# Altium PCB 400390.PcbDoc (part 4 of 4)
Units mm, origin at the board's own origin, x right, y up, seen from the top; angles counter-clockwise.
Board outline 50.8 x 50.4 mm, 4 copper layers (Top Layer, Mid Layer 1, Mid Layer 2, Bottom Layer), stack 1.507 mm thick; 236 components, 197 nets, 1131 pads, 994 vias.
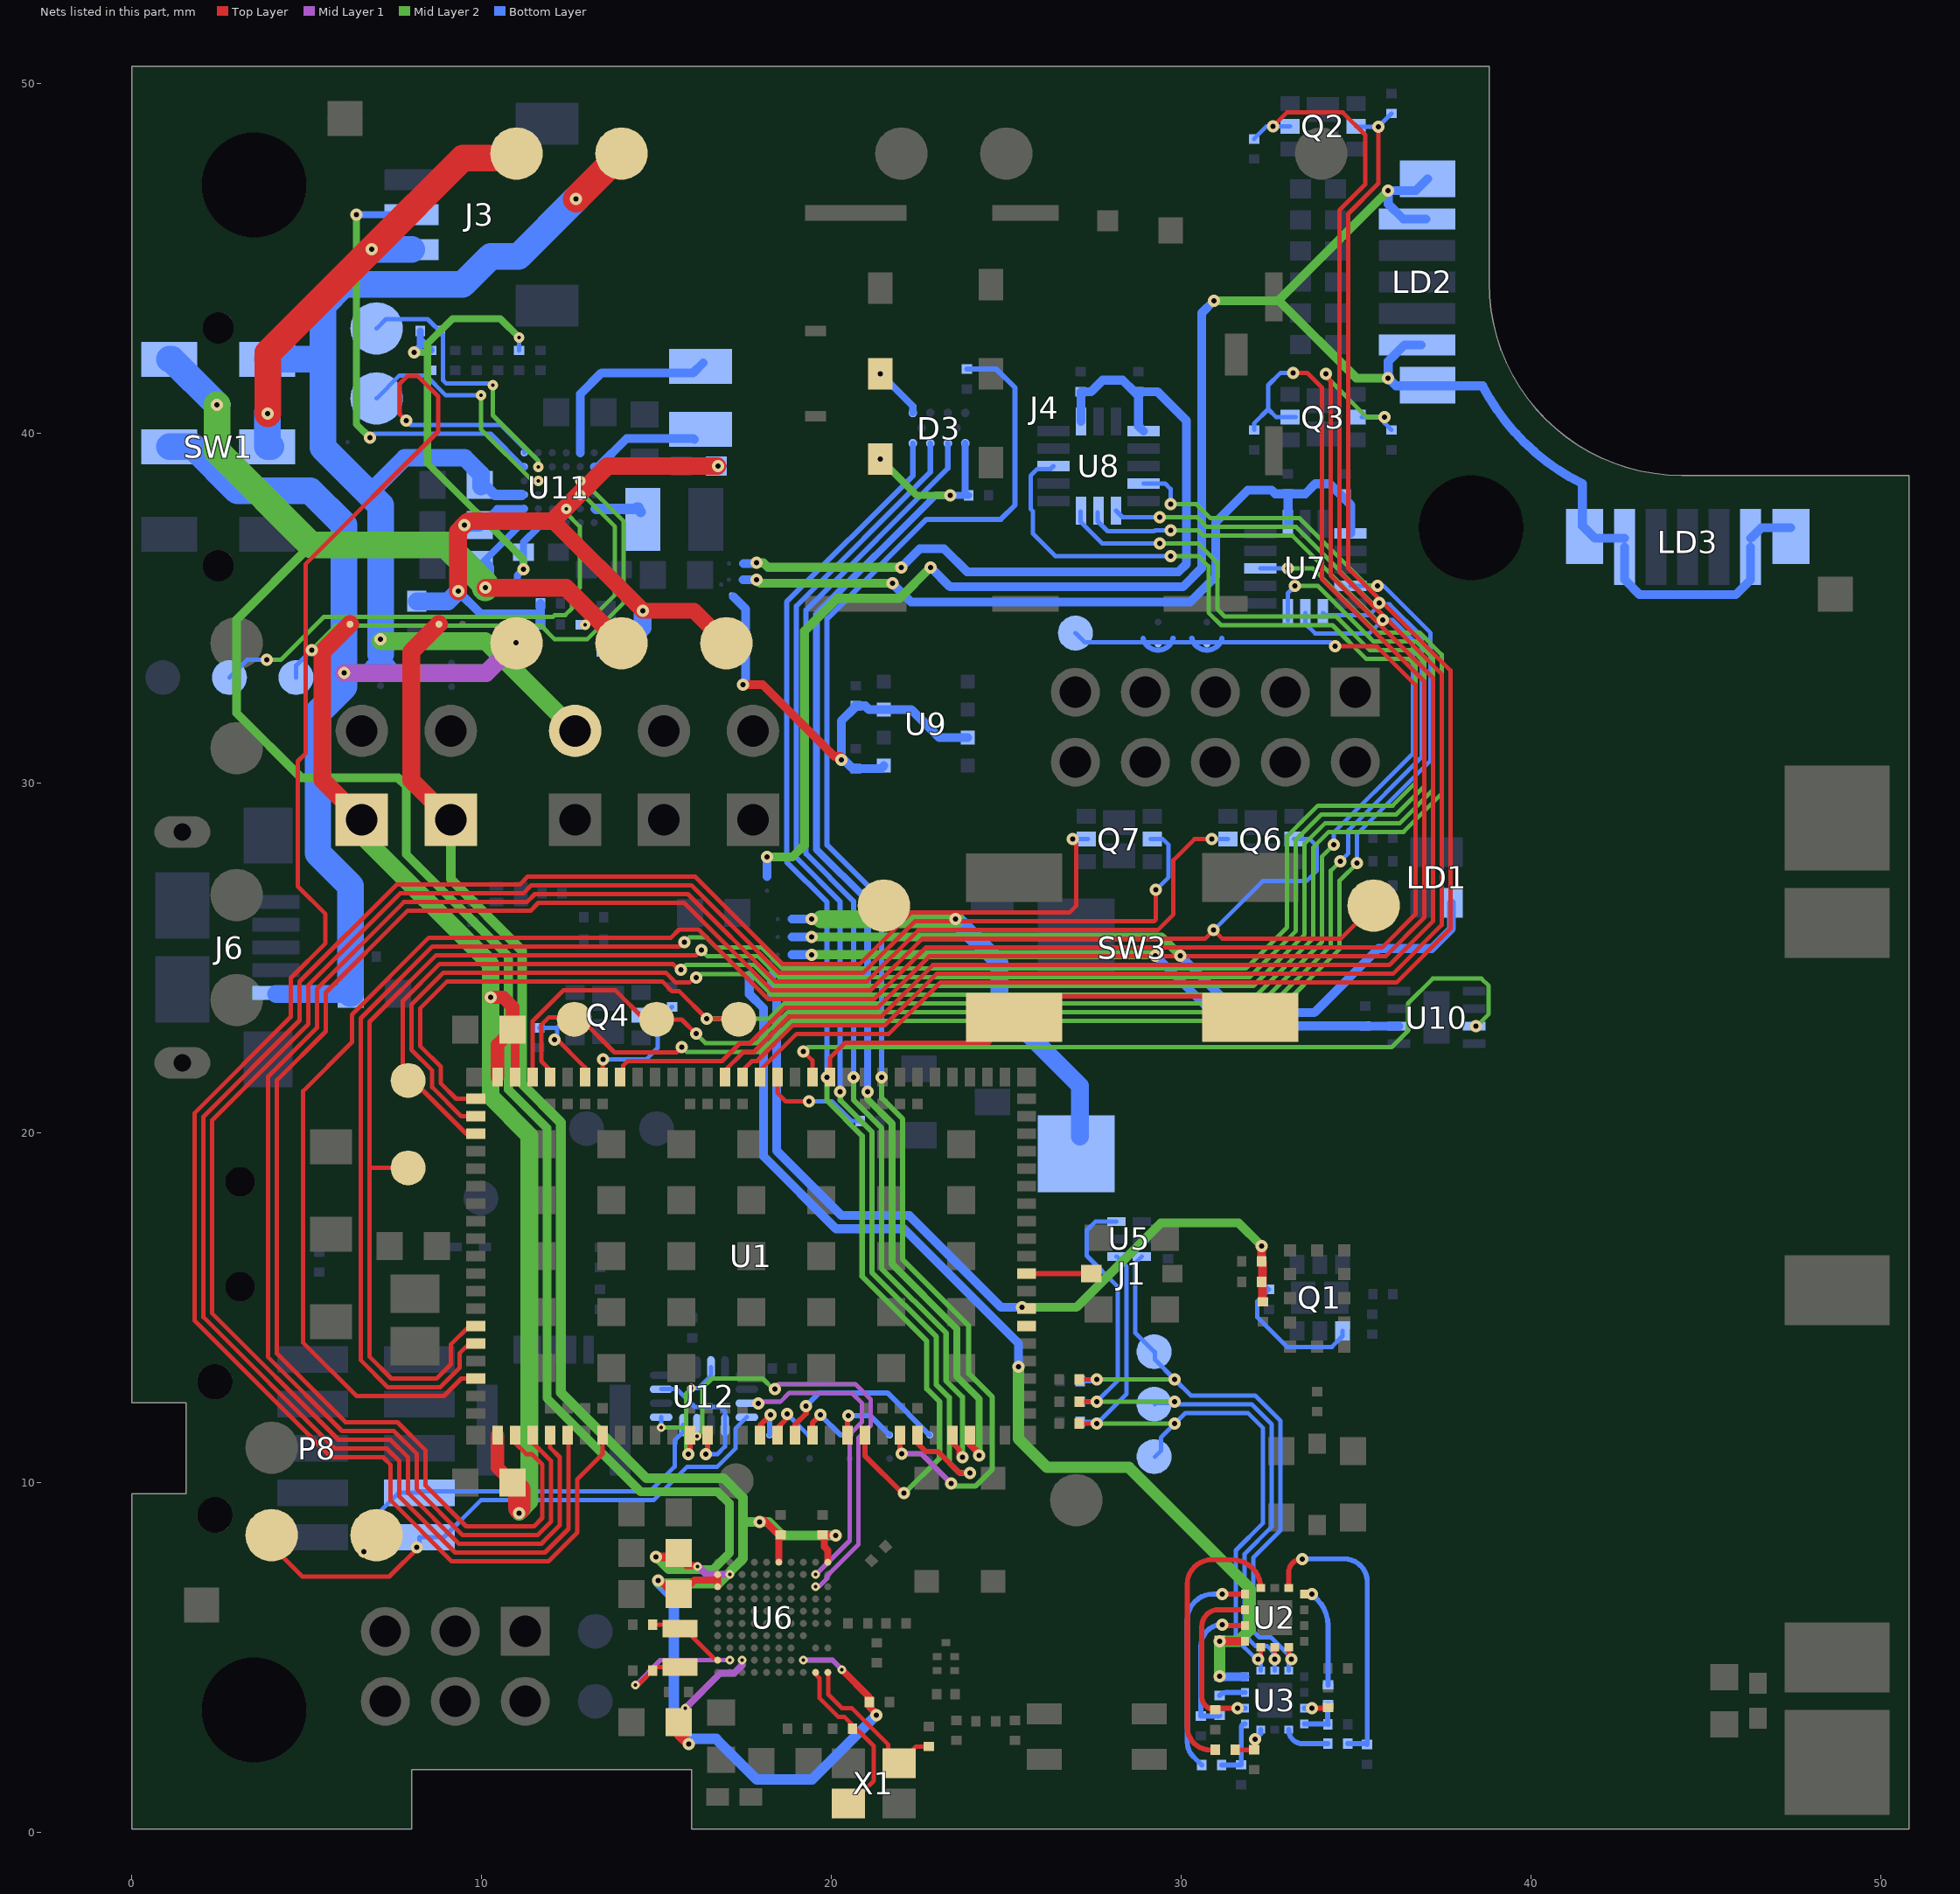
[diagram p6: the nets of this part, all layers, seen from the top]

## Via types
v1: diameter 0.35, hole 0.15, Top Layer to Bottom Layer, tented both sides, 565 vias
v2: diameter 0.35, hole 0.15, Top Layer to Mid Layer 1, tented both sides, 201 vias
v3: diameter 0.35, hole 0.15, Mid Layer 2 to Bottom Layer, tented both sides, 153 vias
v4: diameter 0.25, hole 0.1, Top Layer to Mid Layer 1, tented both sides, 35 vias
v5: diameter 0.3, hole 0.1, Mid Layer 2 to Bottom Layer, tented both sides, 26 vias
v6: diameter 0.25, hole 0.1, Mid Layer 2 to Bottom Layer, tented both sides, 5 vias
v7: diameter 0.35, hole 0.15, Top Layer to Mid Layer 1, 4 vias
v8: diameter 0.3, hole 0.1, Top Layer to Mid Layer 1, tented both sides, 3 vias
v9: diameter 0.61, hole 0.305, Top Layer to Bottom Layer, tented both sides, 2 vias

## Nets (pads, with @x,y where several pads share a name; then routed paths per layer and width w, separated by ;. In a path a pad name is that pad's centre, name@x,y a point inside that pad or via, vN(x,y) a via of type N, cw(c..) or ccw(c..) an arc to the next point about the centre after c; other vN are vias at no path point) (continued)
nRF52_SWDCLK: U6.H2 U12.3 | length 12.9
  Mid Layer 1 w0.125: v1@18.339,12.624 v1@18.364,12.649 ; v1@18.339,12.675 18.481,12.817 20.689,12.817 21.129,12.377 21.129,11.638 20.774,11.284 20.774,8.235 19.884,7.345 ; v4(19.547,7.026) 19.639,7.026 19.884,7.271 19.884,7.345 ; 19.86,7.301 19.86,7.32 19.884,7.345
  Mid Layer 2 w0.125: v6(16.158,11.325) 16.315,11.482 16.315,12.708 16.586,12.979 18.034,12.979 v1@18.339,12.675
  other v1: 18.39,12.675
nRF52_SWDIO: U6.J2 U12.15 | length 8.7
  Mid Layer 1 w0.125: v1(17.907,12.268) 17.951,12.312 18.54,12.312 18.795,12.567 20.585,12.567 20.879,12.273 20.879,11.742 20.524,11.387 20.524,8.338 19.562,7.376 v4(19.547,7.376)
nRF91_SWDCLK: U1.33 U12.5 U12.11 | length 4.5
  Top Layer w0.15: v1(15.906,10.82) 15.956,10.871 U1.33@15.956,11.357
  Mid Layer 2 w0.125: v6(15.133,11.584) 15.844,11.584 15.845,11.582 ; v1(15.906,10.82) 15.845,10.881 15.845,11.582 ; v6(16.002,12.7) 15.845,12.543 15.845,11.582
  Bottom Layer w0.125: v6(15.133,11.584) U12.5@15.133,11.871 ; v6(16.002,12.7) 16.197,12.7 16.558,13.061 U12.11@16.558,13.296
nRF91_SWDIO: U1.34 U12.1 U12.7 | length 4.2
  Top Layer w0.15: v1@16.456,10.922 U1.34@16.456,11.357
  Bottom Layer w0.125: U12.7@15.133,12.671 15.587,12.671 16.099,12.16 16.837,12.16 16.958,12.04 U12.1@16.958,11.646 16.958,11.031 16.747,10.82 v1(16.406,10.82)
P0.00: Q3.2 R44.2 U1.95 | length 45.6
  Top Layer w0.125: U1.95@13.956,21.597 14.043,21.684 14.043,21.922 14.176,22.055 16.874,22.055 17.374,22.555 17.658,22.555 18.685,23.581 21.33,23.581 22.8,25.05 35.843,25.05 36.944,26.151 36.944,32.913 34.023,35.834 34.023,41.309 33.6,41.732 v1(33.198,41.732)
  Bottom Layer w0.125: R44.2@32.09,40.097 32.09,40.294 32.487,40.691 ; v1(33.198,41.732) 32.842,41.732 32.487,41.377 32.487,40.691 ; Q3.2@33.269,40.462 Q3.2@33.106,40.462 32.715,40.462 32.487,40.691
P0.01: Q4.2 R45.2 U1.96 | length 4.1
  Top Layer w0.125: U1.96@13.456,21.597 13.456,21.906 13.475,21.925 v1(13.475,22.1)
  Bottom Layer w0.125: v1(13.475,22.1) 14.705,22.1 15.037,22.432 15.037,23.338 15.066,23.368 ; Q4.2@14.559,23.368 15.066,23.368 ; R45.2@15.448,23.606 15.21,23.368 15.066,23.368
P0.02: Q4.5 R46.2 U1.97 | length 3
  Top Layer w0.125: v1@12.09,22.738 12.956,21.872 U1.97@12.956,21.597
  Bottom Layer w0.125: R46.2@11.653,23.003 12.157,23.003 ; v1(12.09,22.661) 12.157,22.728 12.157,23.003 ; Q4.5@12.669,23.368 12.522,23.368 12.157,23.003
P0.03: TP34.1 U1.99 U7.4 U8.4 | length 47.4
  Top Layer w0.125: U1.99@11.956,21.597 11.956,21.801 11.706,22.051 11.706,23.087 11.917,23.299 12.801,23.299 13.796,22.305 15.58,22.305 v1(15.725,22.45)
  Mid Layer 2 w0.125: v1(15.725,22.45) 15.857,22.318 17.974,22.318 18.859,23.203 32.474,23.203 34.528,25.257 34.528,27.213 v3(35.026,27.71) ; v3(29.693,37.974) 30.433,37.974 30.836,37.572 33.387,37.572 35.315,35.644 v3(35.611,35.644)
  Bottom Layer w0.125: U8.4@28.923,38.565 29.54,38.565 29.693,38.412 v3(29.693,37.974) ; U7.4@34.841,35.644 v3(35.611,35.644) 35.776,35.644 37.127,34.294 37.127,30.647 35.026,28.546 v3(35.026,27.71)
P0.04: TP35.1 U1.100 U7.6 U8.6 | length 48.5
  Top Layer w0.125: U1.100@11.456,21.597 11.456,23.191 12.346,24.081 13.819,24.081 14.659,23.241 15.723,23.241 v1(16.129,22.835)
  Mid Layer 2 w0.125: v1(16.129,22.835) 16.396,22.568 17.87,22.568 18.755,23.453 32.37,23.453 34.278,25.361 34.278,27.496 v3(34.544,27.762) ; v3(29.388,37.601) 30.453,37.601 30.732,37.322 33.283,37.322 35.455,35.15 v3@35.614,35.15
  Bottom Layer w0.125: U8.6@28.135,37.79 28.324,37.601 v3(29.388,37.601) ; U7.6@34.053,34.869 34.116,34.807 35.381,34.807 35.545,34.97 35.545,34.975 35.662,35.092 v3(35.662,35.153) 35.705,35.11 35.957,35.11 36.877,34.19 36.877,30.75 34.776,28.649 34.776,27.994 v3(34.544,27.762)
P0.05: TP36.1 U1.2 U7.7 U8.7 | length 55
  Top Layer w0.125: U1.2@9.836,20.977 9.272,20.977 8.838,21.411 8.838,21.888 8.251,22.475 8.251,23.569 9.013,24.331 15.164,24.331 15.446,24.049 15.651,24.049 v1(16.434,23.266) 17.334,23.266 TP36.1@17.35,23.25
  Mid Layer 2 w0.125: v1(16.434,23.266) 18.215,23.266 18.651,23.703 32.266,23.703 34.028,25.464 34.028,27.907 v3(34.366,28.245) ; v3(29.693,37.228) 30.472,37.228 30.628,37.072 33.18,37.072 35.581,34.671
  Bottom Layer w0.125: U8.7@27.61,37.744 27.61,37.49 27.897,37.203 29.222,37.203 29.222,37.218 29.25,37.218 29.261,37.228 v3(29.693,37.228) ; U7.7@33.553,34.869 33.553,34.554 33.826,34.282 35.376,34.282 v3(35.765,34.671) 36.042,34.671 36.627,34.087 36.627,30.854 34.366,28.593 v3(34.366,28.245)
P0.06: U1.3 U7.11 | length 48.6
  Top Layer w0.125: U1.3@9.836,20.477 9.418,20.477 8.588,21.308 8.588,21.785 7.999,22.373 7.999,23.671 8.909,24.581 15.267,24.581 15.549,24.299 15.943,24.299 16.079,24.435 v1(16.129,24.435)
  Mid Layer 2 w0.125: v1(16.129,24.435) 16.238,24.543 17.697,24.543 18.288,23.953 32.163,23.953 33.778,25.568 33.778,28.169 34.216,28.607 36.354,28.607 37.444,29.697 37.444,33.673 36.809,34.308 35.59,34.308 33.754,36.144 v3(33.045,36.144)
  Bottom Layer w0.125: U7.11@32.266,36.144 v3(33.045,36.144)
P0.07: TP37.1 U1.4 U7.8 | length 48.6
  Top Layer w0.125: U1.4@9.836,19.977 9.562,19.977 7.747,21.792 7.747,23.772 8.805,24.831 15.469,24.831 15.636,24.663 v1(15.697,24.663)
  Mid Layer 2 w0.125: v1(15.697,24.663) 15.831,24.797 17.797,24.797 18.392,24.203 32.059,24.203 33.528,25.671 33.528,28.273 34.112,28.857 36.251,28.857 37.194,29.8 37.194,33.57 36.705,34.058 35.486,34.058 33.908,35.636 v3(33.249,35.636)
  Bottom Layer w0.125: U7.8@33.053,34.646 U7.8@33.053,34.869 33.053,35.441 v3(33.249,35.636)
P0.08: TP38.1 U1.15 U8.8 | length 66.1
  Top Layer w0.125: TP38.1@7.9,19 6.8,19 ; U1.15@9.836,14.477 9.651,14.477 9.128,13.955 9.128,13.392 8.714,12.977 7.423,12.977 6.8,13.6 6.8,19 ; v1(16.281,25.222) 16.14,25.081 8.702,25.081 6.798,23.176 6.798,22.6 6.8,22.597 6.8,19
  Mid Layer 2 w0.125: v1(16.281,25.222) 16.456,25.047 17.901,25.047 18.495,24.453 31.956,24.453 33.278,25.775 33.278,28.376 34.009,29.107 36.147,29.107 36.944,29.904 36.944,33.466 36.601,33.808 35.383,33.808 34.425,34.766 31.244,34.766 31.032,34.978 31.032,36.304 30.48,36.855 v3(29.388,36.855)
  Bottom Layer w0.125: U8.8@27.127,37.77 27.127,37.465 27.737,36.855 v3(29.388,36.855)
P0.09: U1.16 U8.11 | length 68.4
  Top Layer w0.125: U1.16@9.836,13.977 9.651,13.977 9.378,13.705 9.378,13.288 8.817,12.727 7.319,12.727 6.55,13.496 6.55,22.494 6.548,22.496 6.548,22.699 6.547,22.7 6.547,23.279 8.598,25.331 15.679,25.331 v1(15.799,25.451)
  Mid Layer 2 w0.125: v1(15.799,25.451) 15.933,25.585 16.432,25.585 16.719,25.297 18.004,25.297 18.599,24.703 31.852,24.703 33.028,25.878 33.028,28.48 33.905,29.357 36.044,29.357 36.694,30.007 36.694,33.363 36.498,33.558 35.279,33.558 34.322,34.516 31.141,34.516 30.782,34.874 30.782,36.2 30.489,36.493 v3(29.7,36.493)
  Bottom Layer w0.125: U8.11@26.348,39.065 26.26,38.978 25.883,38.978 25.698,38.793 25.698,37.838 25.763,37.773 25.763,37.128 26.398,36.493 v3(29.7,36.493)
P0.10: SB5.1 SB6.1 TP7.1 U1.18 | length 65.8
  Top Layer w0.125: U1.18@9.836,12.977 9.421,12.977 8.921,12.477 6.426,12.477 4.903,14 4.903,21.199 6.297,22.592 6.297,23.382 8.495,25.581 15.416,25.581 15.649,25.813 16.203,25.813 18.186,23.831 21.227,23.831 22.696,25.3 35.739,25.3 36.694,26.254 36.694,32.809 35.594,33.909 v1(34.392,33.909)
  Bottom Layer w0.125: TP7.1@26.975,34.29 27.233,34.032 28.948,34.032 29.726,34.032 30.345,34.032 31.123,34.032 34.269,34.032 v1(34.392,33.909)
P0.13/AIN0: Q6.2 TP32.1 U1.23 | length 62.4
  Top Layer w0.125: U1.23@10.956,11.357 10.956,11.142 11.278,10.82 11.434,10.82 11.736,10.519 11.736,8.989 11.501,8.754 9.559,8.754 8.4,9.913 8.4,10.925 7.598,11.727 6.115,11.727 4.153,13.689 4.153,21.509 5.547,22.903 5.547,24.015 7.881,26.35 11.399,26.35 11.625,26.575 15.795,26.575 18.289,24.081 21.123,24.081 22.593,25.55 30.675,25.55 v1(30.925,25.8) 31.175,25.55 34.55,25.55 TP32.1@35.5,26.5
  Bottom Layer w0.125: v1(30.925,25.8) 32.325,27.2 33.575,27.2 33.875,27.5 33.875,28.2 33.675,28.4 Q6.2@33.22,28.4
P0.14/AIN1: Q6.5 U1.24 | length 55.5
  Top Layer w0.125: U1.24@11.456,11.357 11.456,11.152 11.986,10.622 11.986,8.885 11.605,8.504 9.456,8.504 8.15,9.81 8.15,10.821 7.494,11.477 6.012,11.477 3.903,13.586 3.903,21.613 5.297,23.007 5.297,24.119 7.778,26.6 11.295,26.6 11.521,26.825 15.898,26.825 18.393,24.331 21.02,24.331 22.489,25.8 29.325,25.8 29.775,26.25 29.775,27.8 30.375,28.4 v1(30.875,28.4)
  Bottom Layer w0.125: v1(30.875,28.4) Q6.5@31.33,28.4
P0.15/AIN2: Q7.2 U1.25 | length 56.6
  Top Layer w0.125: U1.25@11.956,11.357 11.956,11.006 12.236,10.726 12.236,8.782 11.855,8.4 11.708,8.254 9.352,8.254 7.9,9.706 7.9,10.718 7.391,11.227 5.908,11.227 2.3,14.835 2.3,20.363 5.047,23.11 5.047,24.222 7.674,26.85 11.192,26.85 11.417,27.075 16.002,27.075 18.496,24.581 20.916,24.581 22.385,26.05 29.221,26.05 29.275,26.104 v1(29.275,26.95)
  Bottom Layer w0.125: Q7.2@29.12,28.4 Q7.2@29.17,28.4 29.475,28.4 29.638,28.238 29.638,27.313 v1(29.275,26.95)
P0.16/AIN3: Q7.5 TP33.1 U1.26 | length 55.1
  Top Layer w0.125: U1.26@12.456,11.357 12.486,11.327 12.486,8.678 11.812,8.004 9.249,8.004 7.65,9.603 7.65,10.614 7.287,10.977 5.805,10.977 2.05,14.732 2.05,20.467 4.797,23.214 4.797,24.326 7.571,27.1 11.088,27.1 11.314,27.325 16.105,27.325 18.6,24.831 20.812,24.831 22.282,26.3 26.8,26.3 27,26.5 27,28.275 v1@26.875,28.4
  Bottom Layer w0.125: v1@26.875,28.4 v1(26.9,28.4) Q7.5@27.28,28.4 Q7.5@27.33,28.4
P0.17/AIN4: U1.28 U11.A6 | length 54.2
  Top Layer w0.125: v1(7.849,40.361) 7.664,40.545 7.664,41.425 7.876,41.638 8.177,41.638 8.759,41.055 8.759,40.051 4.978,36.271 4.978,30.859 4.747,30.628 4.747,27.049 5.54,26.256 5.54,25.423 4.547,24.429 4.547,23.317 1.8,20.571 1.8,14.628 5.701,10.727 7.184,10.727 7.4,10.511 7.4,9.499 9.145,7.754 11.915,7.754 12.736,8.574 12.736,10.094 13.456,10.814 U1.28@13.456,11.357
  Bottom Layer w0.125: v1(7.849,40.361) 7.97,40.239 10.555,40.239 11.221,39.573 U11.A6@11.221,39.446
P0.21: SB7.2 U1.37 | length 1.3
  Top Layer w0.152: U1.37@17.956,11.357 17.956,11.636 v1(18.261,11.941)
  Bottom Layer w0.152: SB7.2@18.235,11.361 18.235,11.916 v1(18.261,11.941)
P0.22: SB8.2 U1.38 | length 1.6
  Top Layer w0.152: U1.38@18.456,11.357 18.456,11.562 18.735,11.841 v1(18.735,11.967)
  Bottom Layer w0.125: v1(18.735,11.967) 19.341,11.361 SB8.2@19.378,11.361
P0.23: SB9.2 U1.39 | length 5.2
  Top Layer w0.152: U1.39@18.956,11.357 18.956,11.655 19.279,11.978 v1(19.279,12.192) v1@19.279,12.217
  Bottom Layer w0.152: v1(19.279,12.192) 19.655,12.568 21.6,12.568 SB9.2@22.807,11.361
P0.24: SB10.2 U1.40 | length 1.8
  Top Layer w0.152: U1.40@19.456,11.357 19.456,11.709 v1(19.685,11.938)
  Bottom Layer w0.152: v1(19.685,11.938) 20.262,11.361 SB10.2@20.521,11.361
P0.25: SB11.2 U1.42 | length 2
  Top Layer w0.152: U1.42@20.456,11.357 20.456,11.89 v1(20.481,11.916)
  Bottom Layer w0.152: v1(20.481,11.916) 21.109,11.916 SB11.2@21.664,11.361
P0.26: SW3.2 U1.83 | length 13.5
  Top Layer w0.125: U1.83@19.956,21.597 19.956,22.14 20.396,22.581 24.506,22.581 25.826,23.901 31.374,23.901 SW3.2@31.975,23.3
P0.27: U1.84 U10.7 | length 23.1
  Top Layer w0.125: v1(19.202,22.326) 19.456,22.072 U1.84@19.456,21.597
  Mid Layer 2 w0.125: v1(19.202,22.326) 19.328,22.453 36.016,22.453 36.487,22.924 36.487,23.711 37.189,24.412 38.582,24.412 38.788,24.206 38.788,23.4 38.438,23.05 v3(38.426,23.05)
P0.28: R21.2 U1.86 | length 3.2
  Top Layer w0.125: U1.86@18.456,21.597 18.456,21.143 18.694,20.904 v1(19.355,20.904)
  Bottom Layer w0.125: v1(19.355,20.904) 20.015,20.904 20.574,20.345 R21.2@20.822,20.345
P0.29: Q2.5 R41.2 U1.87 | length 47.3
  Top Layer w0.125: U1.87@17.956,21.597 U1.87@17.956,21.782 ; U1.87@17.956,21.791 U1.87@17.956,21.782 ; v3(35.636,48.768) 35.636,47.142 34.773,46.279 34.773,36.144 37.694,33.223 37.694,25.84 36.154,24.3 23.11,24.3 21.641,22.831 19.004,22.831 U1.87@17.956,21.782
  Bottom Layer w0.125: Q2.5@34.996,48.781 35.009,48.768 v3(35.636,48.768) 35.636,48.77 R41.2@36.012,49.146
  other v1: 35.636,48.768
P0.30: Q2.2 R42.2 U1.88 | length 50.2
  Top Layer w0.125: U1.88@17.456,21.597 17.456,21.782 17.728,22.055 17.875,22.055 18.901,23.081 21.537,23.081 23.007,24.55 36.05,24.55 37.444,25.944 37.444,33.12 34.523,36.041 34.523,46.382 35.255,47.115 35.255,48.539 34.62,49.174 33.02,49.174 v1(32.626,48.781)
  Bottom Layer w0.125: R42.2@32.08,48.418 32.443,48.781 v1(32.626,48.781) Q2.2@33.106,48.781
P0.31: Q3.5 R43.2 U1.89 | length 42.5
  Top Layer w0.125: U1.89@16.956,21.597 16.956,21.783 17.478,22.305 17.771,22.305 18.797,23.331 21.434,23.331 22.903,24.8 35.946,24.8 37.194,26.047 37.194,33.016 34.273,35.937 34.273,41.496 v1@34.061,41.707
  Mid Layer 2 w0.125: v1@34.061,41.707 35.306,40.462 v3(35.814,40.462)
  Bottom Layer w0.125: Q3.5@35.159,40.462 v3(35.814,40.462) 35.814,40.295 R43.2@36.012,40.097
  other v1: 34.138,41.707
PGOOD1: R27.2 TP20.1 U11.B5 | length 7.8
  Mid Layer 2 w0.125: v5(10.323,41.374) 10.323,40.514 11.621,39.216 v5(11.621,39.046)
  Bottom Layer w0.125: TP20.1@7,43 7.264,43.264 8.462,43.264 8.903,42.823 8.903,41.516 8.994,41.425 10.272,41.425 v5(10.323,41.374)
PGOOD2: R28.2 TP21.1 U11.C5 | length 6.7
  Mid Layer 2 w0.125: v5(9.985,41.088) 9.985,40.111 11.45,38.646 v5(11.621,38.646)
  Bottom Layer w0.125: TP21.1@7,41 7.656,41.656 8.409,41.656 8.978,41.088 v5(9.985,41.088)
R\E\S\E\T\: TP23.1 U11.E3 | length 13.7
  Mid Layer 2 w0.125: v3(3.861,33.528) 4.265,33.528 5.488,34.751 12.035,34.751 12.09,34.806 12.391,34.806 12.589,35.004 12.589,35.373 12.805,35.589 12.805,37.336 12.421,37.72 v5(12.421,37.846)
  Bottom Layer w0.125: TP23.1@2.794,33.02 3.302,33.528 v3(3.861,33.528)
RF: J1.1 U1.61 | length 1.9
  Top Layer w0.146: U1.61@25.576,15.977 J1.1@27.429,15.977
RF_SW1: R1.2 R6.2 TP2.1 U2.7 U3.7 U5.6 | length 19.3
  Top Layer w0.125: R1.2@27.082,12.954 v1(27.584,12.954) ; U2.7@33.071,5.299 33.071,5.033 v1(33.147,4.957)
  Mid Layer 2 w0.125: v1(27.584,12.954) v3(29.812,12.954)
  Bottom Layer w0.125: R6.2@27.107,12.903 27.43,12.903 27.438,12.911 27.541,12.911 v1(27.584,12.954) ; U5.6@28.876,16.467 28.69,16.281 28.69,14.279 TP2.1@29.225,13.745 ; TP2.1@29.25,13.745 29.25,13.516 v3(29.812,12.954) 30.271,12.495 32.111,12.495 ; 32.111,12.495 32.839,11.767 32.839,8.639 32.059,7.858 32.059,5.743 32.221,5.581 32.559,5.581 33.147,4.993 v1(33.147,4.957) 33.071,4.88 U3.7@33.071,4.626
RF_SW2: R2.2 R5.2 TP3.1 U2.6 U3.6 U5.3 | length 21.6
  Top Layer w0.125: R2.2@27.082,12.319 v1(27.584,12.319) ; v1(32.671,4.957) U2.6@32.671,5.299
  Mid Layer 2 w0.125: v1(27.584,12.319) v3(29.812,12.319)
  Bottom Layer w0.125: R5.2@27.107,12.319 v1(27.584,12.319) 28.19,12.925 28.19,15.6 27.298,16.492 27.298,17.214 27.551,17.467 U5.3@28.151,17.467 ; TP3.1@29.25,12.245 29.287,12.282 29.774,12.282 v3(29.812,12.319) 29.886,12.245 32.008,12.245 32.589,11.664 32.589,8.742 31.809,7.961 31.809,5.64 32.117,5.331 32.456,5.331 32.671,5.116 v1(32.671,4.957) U3.6@32.671,4.626
RF_SW3: R3.2 R4.2 TP4.1 U2.5 U3.5 U5.1 | length 20.3
  Top Layer w0.125: R3.2@27.082,11.684 v1(27.584,11.684) ; v1(32.195,4.957) 32.271,5.033 U2.5@32.271,5.299
  Mid Layer 2 w0.125: v1(27.584,11.684) v3(29.812,11.684)
  Bottom Layer w0.125: R4.2@27.107,11.735 v1@27.43,11.735 ; v1(27.584,11.684) 28.44,12.54 28.44,16.178 U5.1@28.151,16.467 ; TP4.1@29.25,10.745 29.417,10.912 29.417,11.29 v3(29.812,11.684) 30.122,11.995 31.905,11.995 32.339,11.56 32.339,8.846 31.559,8.065 31.559,5.536 32.138,4.957 v1(32.195,4.957) 32.271,4.88 U3.5@32.271,4.626
RST_1: D3.C1 J4.C2 | length 1.5
  Bottom Layer w0.203: v1(21.394,41.708) 22.328,40.775 D3.C1@22.328,40.592
SCLK: U1.58
SDATA: U1.59 | length 0
SIM_1V8: C54.1 D3.A4 J4.C1 U1.49 | length 36.3
  Top Layer w0.2: U1.49@23.956,11.357 23.956,11.094 v1@24.25,10.8
  Mid Layer 2 w0.2: v3(21.031,21.184) 21.031,20.972 21.735,20.268 21.735,16.251 23.581,14.405 23.581,13.039 24.225,12.395 v1(24.225,10.775) ; v1(21.394,39.268) 22.436,38.227 v3(23.393,38.227)
  Bottom Layer w0.2: v3(21.031,21.184) 21.032,26.65 19.576,28.106 19.576,34.824 22.978,38.227 v3(23.393,38.227) C54.1@23.828,38.227 ; D3.A4@23.828,39.712 C54.1@23.828,38.227 ; C54.1@23.921,38.227 C54.1@23.828,38.227
SIM_CLK: D3.A2 U1.46 | length 35.4
  Top Layer w0.152: U1.46@22.456,11.357 22.456,11.139 22.709,10.886 23.05,10.886 23.662,10.274 v1(23.957,10.274) ; v1@23.957,10.325 v1@24.008,10.325
  Mid Layer 2 w0.152: v3(20.253,21.184) 20.253,20.932 21.156,20.029 21.156,16.012 23.002,14.166 23.002,12.799 23.368,12.433 23.368,10.568 23.662,10.274 v1(23.957,10.274) ; v1@23.957,10.325 v1@24.008,10.325
  Bottom Layer w0.152: v3@20.25,21.184 20.25,26.613 18.997,27.866 18.997,35.064 22.828,38.895 D3.A2@22.828,39.712
SIM_DET: R38.2 U1.45 | length 41.7
  Top Layer w0.152: U1.45@21.956,11.357 21.956,10.915 v2@22.047,10.824
  Mid Layer 1 w0.152: v2(22.015,10.824) 22.577,10.824 v1(23.419,9.982)
  Mid Layer 2 w0.152: v3(21.438,21.59) 21.438,20.991 22.036,20.393 22.036,16.376 23.927,14.486 23.927,13.119 24.601,12.445 24.601,10.386 24.113,9.898 23.503,9.898 v1(23.419,9.982)
  Bottom Layer w0.152: v3(21.438,21.59) 21.438,26.67 19.877,28.231 19.877,34.7 22.719,37.541 24.841,37.541 25.248,37.948 25.248,41.304 24.714,41.837 R38.2@23.878,41.837
SIM_IO: D3.A3 U1.48 | length 33.1
  Top Layer w0.152: U1.48@23.456,11.357 23.456,11.144 23.643,10.957 v1@23.643,10.825
  Mid Layer 2 w0.152: v3(20.632,21.59) 20.632,20.945 21.434,20.143 21.434,16.127 23.28,14.28 23.28,12.914 23.745,12.449 v1(23.745,10.723)
  Bottom Layer w0.152: v3(20.632,21.59) 20.632,26.624 19.275,27.981 19.275,34.949 23.328,39.003 D3.A3@23.328,39.712
SIM_RST: D3.A1 U1.43 | length 36
  Top Layer w0.152: U1.43@20.956,11.357 20.956,10.77 22.023,9.703 v1(22.073,9.703)
  Mid Layer 2 w0.152: v3(19.874,21.59) v3@19.874,21.488 ; v3@19.976,21.59 v3@19.874,21.488 ; v1(22.073,9.703) 22.096,9.703 23.091,10.698 23.091,12.318 22.725,12.684 22.725,14.051 20.879,15.897 20.879,19.914 19.874,20.918 v3@19.874,21.488
  Bottom Layer w0.152: v3(19.874,21.59) 19.874,26.597 18.72,27.751 18.72,35.179 22.328,38.787 D3.A1@22.328,39.712
STP: TP22.1 U11.C2 | length 14.8
  Mid Layer 2 w0.125: v3(5.147,33.807) 5.841,34.501 11.701,34.501 12.082,34.121 13.026,34.121 14.064,35.158 14.064,37.48 12.898,38.646 v5(12.821,38.646)
  Bottom Layer w0.125: TP22.1@4.699,33.02 4.699,33.359 v3(5.147,33.807)
SW1: L13.1 U11.E1 | length 1.4
  Bottom Layer w0.3: U11.E1@13.271,37.846 L13.1@14.431,37.846 ; L13.1@14.481,37.871 14.431,37.871 L13.1@14.551,37.751
SW2A: L14.1 U11.B1 | length 3.2
  Bottom Layer w0.254: U11.B1@13.225,39.036 13.331,39.036 14.148,39.853 16.059,39.853 L14.1@16.081,39.83
SW2B: L14.2 U11.A2 | length 5.6
  Bottom Layer w0.152: U11.A2@12.802,39.443 U11.A2@12.802,39.446
  Bottom Layer w0.25: U11.A2@12.821,39.446 12.821,41.123 13.43,41.732 16.053,41.732 L14.2@16.332,42.012
SWDCLK: P8.4 TP29.1 U12.4 | length 11.6
  Bottom Layer w0.125: v1(6.629,8.026) 6.629,8.712 7.627,9.71 P8.4@8.225,9.71 8.272,9.757 14.822,9.757 15.519,10.455 15.519,11.201 15.758,11.44 U12.4@15.758,11.646
SWDIO: P8.2 TP27.1 U12.16 | length 16.6
  Top Layer w0.125: TP27.1@4,8.5 4,8.192 4.877,7.315 7.361,7.315 v1@8.225,8.179
  Bottom Layer w0.125: P8.2@8.225,8.179 P8.2@8.225,8.44 8.923,8.44 9.988,9.505 14.926,9.505 15.878,10.457 16.74,10.457 17.256,10.973 17.256,11.545 U12.16@17.583,11.871
  other v1: 8.149,8.153
T1A: L7.2 R10.1 U3.14 | length 1.2
  Top Layer w0.146: R10.1@31.539,2.359 32.098,2.359 32.112,2.373 v1(32.112,2.664)
  Bottom Layer w0.146: v1(32.112,2.664) 32.271,2.823 U3.14@32.271,2.936
T1F: R10.2 U2.14 | length 8.2
  Top Layer w0.146: R10.2@30.969,2.359 30.831,2.359 cw(c30.831,3.019) 30.171,3.019 30.171,7.098 cw(c30.868,7.098) 30.868,7.795 31.465,7.795 cw(c31.465,6.989) U2.14@32.271,6.989
T2A: C10.1 L6.2 U3.1 | length 1.8
  Bottom Layer w0.146: C10.1@31.153,1.927 31.7,1.927 L6.2@31.706,1.933 ; L6.2@31.706,1.933 ccw(c31.679,1.96) 31.717,1.96 31.717,2.997 cw(c31.826,2.997) U3.1@31.826,3.106
T2F: C10.2 U2.1 | length 6.4
  Top Layer w0.146: v1(31.172,6.819) U2.1@31.826,6.819
  Bottom Layer w0.146: C10.2@30.583,1.927 30.346,2.163 cw(c30.77,2.588) 30.171,2.588 30.171,6.067 cw(c30.922,6.067) 30.922,6.819 v1(31.172,6.819)
T3F: C12.2 U2.2 U3.2 | length 5
  Top Layer w0.146: v1(31.608,3.556) 31.018,3.556 ccw(c31.018,3.508) C12.2@30.969,3.508 cw(c30.969,3.889) 30.588,3.889 30.588,5.89 cw(c31.067,5.89) 31.067,6.369 U2.2@31.826,6.369
  Bottom Layer w0.146: v1(31.608,3.556) U3.2@31.826,3.556
T4A: C9.1 U3.3 | length 0.8
  Bottom Layer w0.146: C9.1@31.096,3.914 cw(c31.319,3.691) 31.203,3.984 cw(c31.319,3.691) 31.319,4.006 U3.3@31.826,4.006
T4F: C9.2 L4.2 U2.3 | length 4.2
  Top Layer w0.146: v1@31.172,5.919 U2.3@31.826,5.919
  Bottom Layer w0.146: C9.2@31.096,3.344 cw(c31.062,3.378) 31.062,3.33 L4.2@30.563,3.33 30.563,5.334 cw(c31.172,5.334) v1(31.172,5.944)
T5A: C11.1 U3.12 | length 1.3
  Bottom Layer w0.146: U3.12@33.071,2.936 ccw(c33.471,2.936) 33.096,2.798 ccw(c33.471,2.936) 33.471,2.537 C11.1@34.189,2.537
T5F: C11.2 L5.2 U2.12 | length 8.5
  Top Layer w0.146: U2.12@33.071,6.989 33.071,7.433 cw(c33.458,7.433) v1(33.458,7.82)
  Bottom Layer w0.146: v1(33.458,7.82) 34.66,7.82 cw(c34.66,7.161) 35.318,7.161 L5.2@35.318,2.537 ; C11.2@34.759,2.537 35.293,2.537 L5.2@35.313,2.517
T6A: C14.2 R9.1 U3.11 | length 1.2
  Bottom Layer w0.146: U3.11@33.516,3.106 34.179,3.106 C14.2@34.189,3.096 ; C14.2@34.195,3.09 C14.2@34.189,3.096 ; R9.1@34.195,3.649 34.189,3.643 C14.2@34.189,3.096
T6F: R9.2 U2.11 | length 3
  Top Layer w0.146: U2.11@33.516,6.819 v1(33.734,6.819)
  Bottom Layer w0.146: v1(33.734,6.819) 33.882,6.671 cw(c33.126,5.915) 34.195,5.915 R9.2@34.195,4.219
T7A: L3.2 U3.10 | length 0.7
  Top Layer w0.146: v1(33.734,3.556) L3.2@34.195,3.556
  Bottom Layer w0.146: U3.10@33.516,3.556 v1(33.734,3.556)
THR: J3.2 U11.B6 | length 13.2
  Mid Layer 2 w0.2: v3(6.426,46.253) 6.426,40.259 v3(6.807,39.878)
  Bottom Layer w0.125: v3(6.807,39.878) 6.918,39.989 10.264,39.989 11.207,39.046 U11.B6@11.221,39.046
  Bottom Layer w0.152: U11.B6@11.207,39.046 11.193,39.046 U11.B6@11.218,39.021
  Bottom Layer w0.2: v3(6.426,46.253) J3.2@8.153,46.253
VBUS: C33.1 C53.2 SW1.3 TP12.1 U6.J9 U11.F6 | length 62.8
  Top Layer w0.2: C33.1@15.638,7.86 15.866,7.631 v4@16.17,7.631
  Top Layer w0.254: v1(14.986,7.874) 15.623,7.874 C33.1@15.638,7.86
  Top Layer w0.508: v1(10.109,35.585) 12.415,35.585 TP12.1@14,34
  Mid Layer 1 w0.2: v4@16.17,7.631 16.425,7.376 v4(17.097,7.376)
  Mid Layer 2 w0.254: 5.131,36.805 2.997,34.671 2.997,32.004 4.851,30.15 7.62,30.15 7.849,29.921 7.849,27.965 10.768,25.046 10.768,21.241 11.875,20.134 11.875,16.589 11.875,12.413 14.55,9.737 16.755,9.737 17.084,9.408 17.084,7.986 16.61,7.512 15.348,7.512 v1(14.986,7.874)
  Mid Layer 2 w0.762: v1(2.438,40.818) 2.438,39.497 5.131,36.805 8.992,36.805 10.109,35.687 v1(10.109,35.585)
  Bottom Layer w0.203: C53.2@9.949,36.236 C53.2@9.965,36.236 ; C53.2@9.957,36.228 C53.2@9.965,36.236 ; C53.2@10.067,36.236 C53.2@9.965,36.236 ; U11.F6@11.221,37.446 11.175,37.446 C53.2@9.965,36.236
  Bottom Layer w0.508: v1(10.109,35.585) C53.2@10.109,36.152
  Bottom Layer w0.762: SW1.3@1.075,42.12 1.136,42.12 v1(2.438,40.818)
  other v4: 16.17,7.606
VBUS': C43.1 C44.1 J6.1 SW1.2 TP11.1 | length 27.4
  Mid Layer 1 w0.508: v1(6.071,33.147) 10.126,33.147 v2(10.989,34.011)
  Bottom Layer w0.508: J6.1@4.125,23.975 C43.1@6.237,23.975
  Bottom Layer w0.762: SW1.2@1.075,39.62 1.757,39.62 3.023,38.354 5.105,38.354 6.071,37.389 v1(6.071,33.147) 6.071,32.764 5.323,32.016 5.323,27.996 6.256,27.063 6.259,27.063 C43.1@6.259,23.978
VDD: C52.2 R27.1 R28.1 R33.2 R34.1 U11.F5 | length 14.6
  Mid Layer 2 w0.203: v3(8.077,42.316) 8.428,42.316 8.453,42.342 ; v5(11.078,42.739) 10.535,43.282 9.169,43.282 8.453,42.566 8.453,42.342 ; v3(11.201,36.119) 11.201,36.398 8.453,39.146 8.453,42.342
  Bottom Layer w0.125: R33.2@11.078,42.369 v5(11.078,42.739)
  Bottom Layer w0.203: v3(8.077,42.316) 8.249,42.489 8.249,42.683 ; R27.1@8.249,42.926 8.249,42.683 ; R28.1@8.56,42.373 8.249,42.683 ; R34.1@11.018,35.687 11.018,35.935 v3(11.201,36.119) 11.201,36.6 11.201,36.888 11.621,37.308 U11.F5@11.621,37.446
VDD_ADXL362: C38.2 C39.2 ST8.2 U8.1 U8.14 | length 23.1
  Mid Layer 2 w0.254: v3(17.856,36.297) 18.059,36.297 18.186,36.17 v3(21.996,36.17)
  Bottom Layer w0.254: ST8.2@17.483,36.279 v3@17.818,36.279 ; v3(21.996,36.17) 22.53,36.703 23.216,36.703 23.876,36.043 29.921,36.043 30.15,36.271 30.15,40.361 29.317,41.193 C39.2@28.778,41.193 C39.2@28.651,41.193 ; U8.14@27.135,40.34 C38.2@27.135,41.185 ; C38.2@27.135,41.193 27.426,41.193 27.754,41.521 28.323,41.521 C39.2@28.651,41.193 ; U8.1@28.923,40.065 28.778,40.21 28.778,41.066 C39.2@28.651,41.193
VDD_ADXL372: C36.2 C37.2 ST7.2 U7.1 U7.14 | length 21.9
  Mid Layer 2 w0.254: v3(17.856,35.814) 17.958,35.712 v3(21.742,35.712)
  Bottom Layer w0.254: ST7.2@17.475,35.814 v3(17.856,35.814) ; v3(21.742,35.712) 22.276,35.179 30.251,35.179 30.988,35.916 30.988,37.465 31.898,38.375 32.587,38.375 32.69,38.272 C36.2@33.045,38.272 ; U7.14@33.053,37.419 33.053,38.264 C36.2@33.045,38.272 ; U7.1@34.841,37.144 34.841,37.955 34.239,38.557 33.833,38.557 33.548,38.272 C36.2@33.045,38.272
VDD_BH: C42.2 ST2.2 U10.2 | length 18.2
  Mid Layer 2 w0.254: v3(19.431,25.095) 29.235,25.095 v3(29.261,25.07)
  Bottom Layer w0.254: ST2.2@18.872,25.095 v3(19.431,25.095) ; v3(29.261,25.07) 31.273,23.058 C42.2@35.255,23.058 ; C42.2@35.255,23.05 U10.2@36.225,23.05
VDD_BME: C40.2 C41.2 ST9.2 U9.2 U9.6 U9.8 | length 13
  Top Layer w0.254: v1(17.475,32.817) 18.035,32.817 20.086,30.765 20.264,30.765 v1@20.282,30.747
  Bottom Layer w0.254: 17.196,35.331 17.551,34.976 17.551,32.893 v1(17.475,32.817) ; U9.8@21.5,30.5 21.415,30.415 C41.2@20.7,30.415 20.692,30.423 20.606,30.423 20.282,30.747 20.282,31.779 20.677,32.173 20.677,32.207 20.685,32.215 C40.2@20.7,32.215 20.708,32.207 20.968,32.207 21.075,32.1 U9.6@21.5,32.1 22.289,32.1 23.089,31.3 U9.2@23.9,31.3
  other v1: 20.282,30.671
VDD_BZR: Bz1.1 D2.1 ST5.2 | length 12.8
  Mid Layer 2 w0.254: v3(19.431,26.111) 19.706,26.111
  Mid Layer 2 w0.508: 19.706,26.111 v3(23.546,26.111)
  Bottom Layer w0.254: ST5.2@18.872,26.111 v3(19.431,26.111) ; D2.1@24.8,23.222 D2.1@24.8,23.65
  Bottom Layer w0.508: v3(23.546,26.111) 24.8,24.857 24.8,23.65 27.1,21.35 Bz1.1@27.1,19.9
VDD_LNA: C5.2 C6.2 L2.2 Q1.4 R8.1 ST6.2 | length 29
  Top Layer w0.254: C6.2@32.301,16.328 v1(32.301,16.764) ; L2.2@32.321,15.166 32.321,15.744 C6.2@32.321,16.309
  Mid Layer 2 w0.254: v3(25.451,15.011) 27,15.011 29.413,17.424 31.64,17.424 v1(32.301,16.764)
  Bottom Layer w0.125: v1(32.301,16.764) 32.301,15.736 32.425,15.612 32.425,15.597 R8.1@32.497,15.525 ; R8.1@32.512,15.525 R8.1@32.497,15.525 ; Q1.4@34.61,14.346 34.61,14.188 34.305,13.883 34.247,13.883 33.672,13.883 33.022,13.883 32.174,14.731 32.174,15.187 32.425,15.438 32.425,15.452 R8.1@32.497,15.525
  Bottom Layer w0.254: ST6.2@18.288,24.511 18.288,23.984 18.438,23.834 18.438,19.487 20.289,17.637 22.229,17.637 24.854,15.011 v3(25.451,15.011)
VDD_LW: LD2.1 LD2.2 LD2.6 LD3.1 LD3.2 LD3.6 ST4.2 | length 59.6
  Mid Layer 2 w0.254: v3(18.161,27.889) 18.887,27.889 19.228,28.23 19.228,34.346 20.168,35.285 21.95,35.285 v3(22.835,36.17) ; v3(30.937,43.79) 32.766,43.79 ; v3(35.916,41.58) 35.001,41.58 32.791,43.79 32.766,43.79 ; v3(35.916,46.939) 32.766,43.79
  Bottom Layer w0.254: ST4.2@18.161,27.33 v3(18.161,27.889) ; v3(22.835,36.17) 23.393,35.611 30.048,35.611 30.582,36.144 30.582,43.434 v3(30.937,43.79) ; LD2.6@36.864,42.528 36.381,42.528 35.916,42.062 v3(35.916,41.58) 36.138,41.358 38.616,41.358 ccw(c44.3,44.3) 41.467,38.56 41.467,37.358 41.825,37 LD3.2@42.675,37 ; LD2.2@36.992,46.128 36.346,46.128 35.916,46.558 v3(35.916,46.939) 36.703,46.939 LD2.1@37.042,47.278 ; LD3.2@42.675,36.75 42.675,35.815 43.104,35.386 45.847,35.386 46.275,35.814 LD3.6@46.275,36.75 ; LD3.6@46.275,37 46.575,37.3 LD3.1@47.425,37.3
VDD_nRF52: C22.1 C23.1 C24.1 C26.1 C27.1 P2.1 SB4.1 U6.B3 U6.B8 U6.H10 U6.J10 U6.K1 U6.K5 | length 60.4
  Top Layer w0.2: v1@15.1,7.203 15.638,6.666 15.638,6.766 16.085,7.214 16.747,7.214 ; U6.H10@16.747,7.026 16.747,7.214 ; U6.J10@16.747,7.376 16.747,7.214 ; v1@18.073,8.925 18.497,8.501 U6.K5@18.497,7.726 ; C24.1@19.745,8.508 20.103,8.508 v1(20.118,8.493) ; C24.1@19.796,8.467 19.796,8.17 19.897,8.068 U6.K1@19.897,7.726 ; v4(20.303,4.652) 21.088,3.868 C26.1@21.088,3.723 21.088,3.586 21.291,3.382 21.291,3.399 v1@21.216,3.474
  Top Layer w0.3: C27.1@15.636,3.15 15.636,2.812 v1(15.925,2.522)
  Top Layer w0.508: SB4.1@8.781,34.544 7.99,33.753 7.99,30.085 P2.1@9.119,28.956
  Mid Layer 1 w0.15: v4(19.197,4.926) 20.03,4.926 v4(20.303,4.652)
  Mid Layer 1 w0.2: v4(15.829,3.556) 16.83,4.558 17.224,4.558 17.447,4.781 v4(17.447,4.926)
  Mid Layer 2 w0.279: P2.1@9.119,28.956 9.119,27.249 11.159,25.209 11.159,21.403 12.266,20.296 12.266,16.751 12.266,12.575 14.713,10.129 16.917,10.129 17.476,9.57 17.476,8.89 ; v1@15.046,7.148 15.059,7.135 15.109,7.135 15.124,7.12 16.772,7.12 17.476,7.824 17.476,8.89 ; v1(20.118,8.493) 18.593,8.493 18.212,8.874 v1(17.946,8.874) 17.492,8.874 17.476,8.89
  Bottom Layer w0.3: v1@15.046,7.148 15.494,6.7 15.494,3.081 15.9,2.675 16.706,2.675 17.869,1.511 19.443,1.511 v1(21.291,3.358)
  other v1: 15.046,7.199
VDD_nRF91: C1.2 C2.2 P1.1 SB3.1 U1.22 U1.101 U1.102 | length 34.9
  Top Layer w0.254: C1.2@10.888,22.954 10.956,22.886 U1.101@10.956,21.597
  Top Layer w0.381: v1(10.262,23.876) 10.617,23.876 10.888,23.605 C1.2@10.888,22.954 10.456,22.521 U1.102@10.456,21.597 ; U1.22@10.456,11.357 10.456,10.432 C2.2@10.888,10
  Top Layer w0.508: SB3.1@6.241,34.544 5.45,33.753 5.45,30.085 P1.1@6.579,28.956
  Top Layer w0.635: C2.2@10.888,10 11.074,9.814 v1@11.074,9.271
  Mid Layer 2 w0.508: P1.1@6.579,28.956 6.579,28.499 10.262,24.816 v1(10.262,23.876) 10.262,21.031 11.369,19.924 11.369,9.466 v1@11.074,9.172
  other v1: 11.074,9.122
VDD_QM: C16.2 C17.2 ST1.2 U2.4 U3.4 | length 30.6
  Top Layer w0.254: C16.2@31.096,5.463 v1(31.101,5.469) U2.4@31.826,5.469
  Mid Layer 2 w0.33: v3(25.349,13.31) 25.349,11.252 26.162,10.439 28.502,10.439 31.956,6.986 31.956,5.784 31.64,5.469 v1(31.101,5.469) 31.096,5.463 v1(31.096,4.462)
  Bottom Layer w0.254: ST1.2@17.653,24.511 17.653,23.973 18.059,23.566 18.059,19.33 20.132,17.258 22.072,17.258 25.349,13.98 v3(25.349,13.31) ; v1(31.096,4.462) 31.101,4.456 U3.4@31.826,4.456
VDD_SENSE: LD1.4 ST3.2 | length 21.5
  Mid Layer 2 w0.254: v3(19.431,25.603) 29.439,25.603 v3(29.972,25.07)
  Bottom Layer w0.254: ST3.2@18.872,25.603 v3(19.431,25.603) ; v3(29.972,25.07) 31.605,23.437 33.8,23.437 35.636,25.273 37.16,25.273 37.725,25.838 LD1.4@37.725,26.575
VID1: R26.1 U11.D2 | length 4.5
  Mid Layer 2 w0.125: v5(12.821,38.246) 12.898,38.246 13.814,37.33 13.814,35.385 v5(12.957,34.529)
VLI-ION: C50.2 P3.2 SB2.2 ST10.2 SW1.6 TP14.1 U11.D6 | length 34.6
  Top Layer w0.762: v1(12.7,46.7) TP14.1@14,48
  Mid Layer 2 w0.508: v3@7.112,34.06 10.111,34.06 P3.2@12.675,31.496
  Bottom Layer w0.3: C50.2@10.102,38.522 10.381,38.243 U11.D6@11.154,38.243
  Bottom Layer w0.5: 6.768,38.289 6.79,38.289 7.798,39.297 9.522,39.297 9.982,38.837 C50.2@9.982,38.481
  Bottom Layer w0.762: SW1.6@3.875,42.12 5.454,42.12 5.461,42.113 ; 7.112,33.68 7.112,33.685 v3(7.112,34.112) 7.112,37.945 6.768,38.289 5.461,39.596 5.461,42.113 ; v1(12.7,46.7) 11.06,45.06 10.262,45.06 9.458,44.256 6.056,44.256 5.461,43.661 5.461,42.113
VLi-Ion': J3.3 SW1.5 TP13.1 | length 13.7
  Top Layer w0.762: v1(3.886,40.564) 3.886,42.291 v1(6.858,45.263) 9.467,47.871 10.857,47.871 11,47.728 TP13.1@11,48
  Bottom Layer w0.762: v1@3.875,40.603 SW1.5@3.875,39.62 SW1.5@3.984,39.62 ; v1(6.858,45.263) 7.995,45.263 J3.3@8,45.258
VSYS: C51.2 R24.2 R25.2 R29.1 R30.1 R31.2 TP17.1 U11.E6 | length 24.4
  Top Layer w0.457: 12.04,37.506 v1@14.613,34.933 ; v1(14.605,34.925) 16.075,34.925 TP17.1@17,34
  Top Layer w0.508: v1(9.331,35.484) 9.331,37.201 v1(9.509,37.379) 9.62,37.49 12.04,37.49 12.04,37.506 13.599,39.065 v1@16.739,39.065
  Bottom Layer w0.203: C51.2@10.021,37.426 10.441,37.846 U11.E6@11.221,37.846
  Bottom Layer w0.254: v1(9.331,35.484) 9.976,34.839 11.682,34.839 ; R30.1@11.682,34.534 11.682,34.839 ; R29.1@11.682,35.144 11.682,34.839
  Bottom Layer w0.381: v1(9.509,37.379) C51.2@9.931,37.379
  Bottom Layer w0.508: R24.2@8.153,35.196 9.044,35.196 v1(9.331,35.484) ; R25.2@13.564,33.917 14.08,33.917 14.605,34.442 v1(14.605,34.925)
  other v1: 16.764,39.065
XC1: C18.1 U6.A1 X1.1 | length 4.7
  Top Layer w0.125: U6.A1@19.897,4.576 19.913,4.561 19.913,3.941 20.296,3.558 20.579,3.558 21.625,2.511 21.625,2.281 X1.1@21.934,1.972 21.984,1.972 22.346,2.334 22.346,2.384 22.42,2.458 C18.1@22.784,2.458
XC2: C19.1 U6.A2 X1.3 | length 4.9
  Top Layer w0.125: U6.A2@19.547,4.576 19.562,4.562 19.562,4.505 19.663,4.404 19.663,3.837 20.192,3.308 20.37,3.308 21.209,2.468 21.209,1.473 20.92,1.184 20.846,1.184 X1.3@20.484,0.822
XL1: C30.1 U6.B9 X2.1 | length 4.5
  Top Layer w0.125: v4(14.402,4.216) 14.471,4.216 14.983,4.728 X2.1@15.672,4.728
  Mid Layer 1 w0.125: v4(14.402,4.216) 14.402,4.218 15.109,4.926 v4(17.097,4.926)
XL2: C31.1 U6.B10 X2.2 | length 2.4
  Top Layer w0.125: C31.1@14.89,5.944 15.697,5.944 X2.2@15.742,5.899 ; X2.2@15.672,5.828 15.788,5.828 16.691,4.926 U6.B10@16.747,4.926 ; U6.B10@16.691,4.926 U6.B10@16.747,4.926
pads on no net: A1.0 A1.3 A1.4 Fid1.0 Fid2.0 Fid3.0 H1. H2. H3. J3.0 J4.C6 J5.0 J5.1 J5.3 J5.5 J6.4 J6.6@1.45,22 J6.6@1.45,28.6 P8.0 P8.6 P8.7 P8.8 P8.10 SW1.0 SW1.1 SW2.0 U1.10 U1.32 U1.51 U1.57 U1.64 U1.70 U1.71 U1.73 U1.104 U1.105 U1.106 U1.107 U1.108 U1.109 U1.110 U1.111 U1.112 U1.113 U1.114 U1.115 U1.116 U1.117 U1.118 U1.119 U1.120 U1.121 U1.122 U1.123 U1.126 U1.127 U2. U2.8 U2.9 U2.10 U3. U3.8 U3.9 U6.B4 U6.B5 U6.B6 U6.C5 U6.C6 U6.C7 U6.C8 U6.C10 U6.E3 U6.E10 U6.F3 U6.F9 U6.G3 U6.G10 U6.H4 U6.H5 U6.H6 U6.H7 U6.H9 U7.2 U7.3 U7.5 U7.10 U7.15 U8.2 U8.3 U8.5 U8.10 U8.15 U10.8 U12.9 U12.13

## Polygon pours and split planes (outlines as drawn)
GND on Mid Layer 2 "Mid_Layer_2-GND" (solid, remove dead copper, pour order 14): 60.004,-4.572 -14.604,-4.572 -14.604,54.331 60.004,54.331
AGND on Mid Layer 2 "Mid Layer 2-AGND" (solid, remove dead copper, pour order 7): 12.983,42.891 8.695,42.891 8.695,35.789 12.983,35.789
GND on Mid Layer 1 "Mid_Layer_1-GND" (solid, remove dead copper, pour order 12): 59.776,-4.724 -14.833,-4.724 -14.833,54.178 59.776,54.178
GND on Top Layer "Top_Layer-GND" (solid, remove dead copper, pour order 10): 59.395,-3.835 -15.214,-3.835 -15.214,55.067 59.395,55.067
GND on Bottom Layer "Bottom_Layer-GND" (solid, remove dead copper, pour order 8): 60.995,-3.988 -6.595,-3.988 -6.595,54.889 60.995,54.889

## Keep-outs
Top Layer:
  circle w0.1: c38.28,37.3 r2.5
Keep-Out Layer:
  circle w0.1: c23.997,0.1 r0.3
  circle w0.1: c24.997,0.1 r0.3
  circle w0.1: c25.997,0.1 r0.3
  circle w0.1: c26,50.5 r0.3
  circle w0.1: c25,50.5 r0.3
  circle w0.1: c24,50.5 r0.3
  circle w0.1: c0,19.6 r0.3
  circle w0.1: c0,18.6 r0.3
  circle w0.1: c0,17.6 r0.3
  circle w0.1: c50.8,17.6 r0.3
  circle w0.1: c50.8,18.6 r0.3
  circle w0.1: c50.8,19.6 r0.3
  lines w0.001: 20.7,28.2 cw(c20.7,28.7) 20.7,29.2 24.2,29.2 ccw(c24.2,29.7) 24.7,29.7 24.7,33.2 ccw(c24.2,33.2) 24.2,33.7 20.7,33.7 cw(c20.7,34.2) 20.7,34.7 24.2,34.7 cw(c24.2,33.2) 25.7,33.2 25.7,29.7 cw(c24.2,29.7) 24.2,28.2 20.7,28.2
  lines w0.1: 0,0.1 8,0.1 8,1.8 16,1.8 16,0.1 50.8,0.1 50.8,38.8 44.3,38.8 cw(c44.3,44.3) 38.8,44.3 38.8,50.5 0,50.5 0,12.28 1.56,12.28 1.56,9.68 0,9.68 0,0.1

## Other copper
Top Layer:
  region net GND: 29.699,3.688 29.471,3.688 29.471,3.103 29.699,3.103
  region net GND: 29.699,2.388 29.471,2.388 29.471,1.803 29.699,1.803
  rectangle net GND: 25.483,1.803 25.711,2.388
  rectangle net ANT_LTE: 45.872,0.5 46.558,1.5
  rectangle net GND: 17.347,5.526 18.947,6.776
  rectangle net GND: 18.747,5.276 18.947,5.726
  pour cut-out: 17.467,2.982 17.467,2.529 17.264,2.529 17.264,2.58 17.264,2.986
  pour cut-out: 18.479,1.883 18.932,1.883 18.932,1.68 18.881,1.68 18.475,1.68
  pour cut-out: 25.591,7.793 29.591,7.793 29.591,0.1 25.591,0.1 25.591,1.793
  region net GND: 20.228,5.626 20.375,5.479 20.375,5.214 19.959,5.214 19.821,5.352 19.821,5.626
Mid Layer 1:
  pour cut-out: 5.687,33.646 5.687,35.424 9.906,35.424 9.906,33.646
  pour cut-out: 32.387,2.68 32.387,1.48 31.787,1.48 31.787,2.68
  pour cut-out: 34.495,4.458 34.495,3.258 33.895,3.258 33.895,4.458
  pour cut-out: 35.074,4.396 33.874,4.396 33.874,4.996 35.074,4.996
  pour cut-out: 31.854,2.059 30.654,2.059 30.654,2.659 31.854,2.659
  pour cut-out: 30.669,2.623 30.669,3.823 31.269,3.823 31.269,2.623
  pour cut-out: 25.183,19.32 25.971,19.32 25.971,18.634 25.183,18.634
  pour cut-out: 25.183,16.32 25.971,16.32 25.971,15.634 25.183,15.634
  pour cut-out: 25.591,7.793 29.591,7.793 29.591,0.1 25.591,0.1 25.591,1.793
Mid Layer 2:
  rectangle net AGND: 12.776,38.938 13.447,39.243
  pour cut-out: 6.248,32.182 6.248,33.96 10.033,33.96 10.033,32.182
  pour cut-out: 35.074,2.796 33.874,2.796 33.874,3.396 35.074,3.396
  pour cut-out: 35.074,2.237 33.874,2.237 33.874,2.837 35.074,2.837
  pour cut-out: 31.468,1.627 30.268,1.627 30.268,2.227 31.468,2.227
  pour cut-out: 30.263,2.445 30.263,3.645 30.863,3.645 30.863,2.445
  pour cut-out: 30.796,3.029 30.796,4.229 31.396,4.229 31.396,3.029
  pour cut-out: 33.895,3.334 33.895,4.534 34.495,4.534 34.495,3.334
  pour cut-out: 35.013,1.632 35.013,2.832 35.613,2.832 35.613,1.632
  pour cut-out: 31.406,1.048 31.406,2.248 32.006,2.248 32.006,1.048
  region net GND: 13.184,39.497 13.184,38.73 13.357,38.557 13.792,38.557 13.818,38.583 13.818,39.497
  pour cut-out: 17.424,12.048 23.749,12.048 23.749,10.033 17.424,10.033
  pour cut-out: 25.591,7.793 29.591,7.793 29.591,0.1 25.591,0.1 25.591,1.793
Bottom Layer:
  region net 1V8: 17.126,38.502 15.729,38.502 15.729,35.581 17.126,35.581
  rectangle net 3V3: 16.891,24.841 18.542,27
  region net GND: 15.225,36.35 13.719,36.35 13.719,35.563 15.225,35.563
  region net AGND: 12.508,36.873 11.84,36.873 11.84,35.931 12.508,35.931
  pour cut-out: 16.956,39.256 16.956,38.672 16.677,38.672 16.677,39.256
  region net GND: 13.221,39.37 13.259,39.37 14.046,40.157 15.037,40.157 15.037,40.869 13.106,40.869 13.106,39.446 13.132,39.421
  region net GND: 13.221,39.446
  pour cut-out: 25.591,7.793 29.591,7.793 29.591,0.1 25.591,0.1 25.591,1.793
Multi-Layer:
  pour cut-out: 20,34.2 20,28.7 24.917,28.7 24.917,34.2

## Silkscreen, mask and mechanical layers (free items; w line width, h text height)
Top Overlay:
  drawing of 57 lines, arcs and shapes, not listed
  text "'.PCBNumber'" at 37.109,49.779 h2.03 r270
  text "'.PCBRevision'" at 36.079,49.696 h0.51 r270
  text "SIM" at 17.221,47.955 h1.78
  text "X" at 34.242,43.947 h1.37
  text "Thingy:91" at 3.302,43.637 h2.41 r270
  text "ON" at 0.254,41.986 h1.78 r270
  text "Y" at 37.606,40.533 h1.37
  text "OFF" at 0.254,39.065 h1.78 r270
  text "4D" at 26.375,33.8 h1.5
  text "3D" at 28.375,33.8 h1.5
  text "2D" at 30.375,33.8 h1.5
  text "1D" at 32.375,33.8 h1.5
  text "1V8" at 34.085,33.8 h1.5
  text "+" at 20.259,31.919 h1.02 r90
  text "IN" at 4.293,31.877 h1.27 r270
  text "OUT" at 4.293,29.87 h1.27 r270
  text "GND" at 19.279,29.87 h1.27 r270
  text "4S" at 26.375,28.5 h1.5
  text "3S" at 28.375,28.5 h1.5
  text "2S" at 30.375,28.5 h1.5
  text "1S" at 32.375,28.5 h1.5
  text "GND" at 33.834,28.5 h1.5
  text "nRF91" at 6.071,27.432 h1.78 r270
  text "nRF52" at 8.611,27.432 h1.78 r270
  text "Li-po" at 12.167,27.432 h1.78 r270
  text "1V8" at 14.707,27.432 h1.78 r270
  text "3V3" at 17.247,27.432 h1.78 r270
  text "nRF91" at 0.6,21.441 h1.34 r270
  text "SWD / SELECT" at 2.575,20.825 h1.34
  text "LTE" at 27.432,17.526 h1.78
  text "nRF52" at 0.6,15.455 h1.34 r270
  text "GPS" at 31.094,11.198 h1.78 r270
Bottom Overlay:
  drawing of 838 lines, arcs and shapes, not listed
  text "Power" at 4.572,44.374 h2.03
  text "ON" at 4.805,40.818 h1.78 r270
  text "OFF" at 4.805,36.576 h1.78 r270
Board Outline:
  lines w0.15: 0,0.1 8,0.1 8,1.8 16,1.8 16,0.1 50.8,0.1 50.8,38.8 44.3,38.8 cw(c44.3,44.3) 38.8,44.3 38.8,50.5 0,50.5 0,12.28 1.56,12.28 1.56,9.68 0,9.68 0,0.1
  lines w0.152: 20.7,28.2 cw(c20.7,28.7) 20.7,29.2 24.2,29.2 ccw(c24.2,29.7) 24.7,29.7 24.7,33.2 ccw(c24.2,33.2) 24.2,33.7 20.7,33.7 cw(c20.7,34.2) 20.7,34.7 24.2,34.7 cw(c24.2,33.2) 25.7,33.2 25.7,29.7 cw(c24.2,29.7) 24.2,28.2 20.7,28.2
Board Other:
  drawing of 2143 lines, arcs and shapes, not listed
Dimension:
  circle w0.1: c38.28,37.3 r1.55
Top Assembly:
  drawing of 43 lines, arcs and shapes, not listed
Bottom Assembly:
  drawing of 874 lines, arcs and shapes, not listed
Top Impedance Info:
  lines w0.146: 19.897,5.976 20.47,5.976 ; 21.046,5.976 21.313,5.976 21.562,5.976 ; 22.132,5.976 22.723,5.976 cw(c22.723,5.425) 23.275,5.425 ; 23.525,3.246 23.525,4.625 ; 23.574,3.206 24.096,3.206 ; 24.697,3.175 25.873,3.175 ; 25.576,15.977 27.429,15.977 ; 25.576,18.977 32.234,18.977 cw(c32.234,17.323) 33.888,17.323 33.888,16.64 ; 29.676,15.977 cw(c29.676,14.737) 30.916,14.737 30.916,10.288 ccw(c32.944,10.288) 31.51,8.854 32.29,8.074 cw(c31.37,7.154) 32.671,7.154 32.671,6.989 ; 30.969,2.359 30.831,2.359 cw(c30.831,3.019) 30.171,3.019 30.171,7.098 cw(c30.868,7.098) 30.868,7.795 31.465,7.795 cw(c31.465,6.989) 32.271,6.989 ; 30.969,3.508 cw(c30.969,3.889) 30.588,3.889 30.588,5.89 cw(c31.067,5.89) 31.067,6.369 31.826,6.369 ; 31.018,3.556 31.608,3.556 ; 31.172,5.919 31.826,5.919 ; 31.172,6.819 31.826,6.819 ; 31.539,2.359 32.098,2.359 32.112,2.373 32.112,2.664 ; 33.071,6.989 33.071,7.433 cw(c33.458,7.433) 33.458,7.82 ; 33.113,13.89 ccw(c33.889,13.89) 33.34,13.342 33.754,12.928 cw(c33.429,12.604) 33.888,12.604 ; 33.516,6.819 33.734,6.819 ; 33.734,3.556 34.195,3.556 ; 33.888,8.794 cw(c33.146,8.052) 34.195,8.052 34.195,4.143 ; 33.888,11.114 33.888,12.044 ; 37.77,0.991 38.577,0.991
  text "50ohm impedance top" at 29.06,-1.778 h0.89
Bottom Impedance Info:
  lines w0.146: 30.583,1.927 30.346,2.163 ; 31.062,3.33 30.563,3.33 ; 31.153,1.927 31.7,1.927 31.706,1.933 ; 31.172,5.944 ccw(c31.172,5.334) 30.563,5.334 30.563,3.33 ; 31.172,6.819 30.922,6.819 ccw(c30.922,6.067) 30.171,6.067 30.171,2.588 ccw(c30.77,2.588) 30.346,2.164 ; 31.319,4.006 31.826,4.006 ; 31.608,3.556 31.826,3.556 ; 31.717,1.96 31.717,2.997 ; 32.112,2.664 32.271,2.823 32.271,2.936 ; 32.671,2.936 32.671,2.736 ccw(c34.417,2.736) 34.417,0.991 37.77,0.991 ; 33.458,7.82 34.66,7.82 cw(c34.66,7.161) 35.318,7.161 35.318,2.537 ; 33.471,2.537 34.189,2.537 ; 33.516,3.106 34.179,3.106 34.189,3.096 ; 33.516,3.556 33.734,3.556 ; 33.734,6.819 33.882,6.671 cw(c33.126,5.915) 34.195,5.915 34.195,4.219 ; 34.195,3.09 34.189,3.096 ; 34.195,3.649 34.189,3.643 34.189,3.096 ; 34.759,2.537 35.293,2.537 35.313,2.517 ; 30.346,2.164 30.346,2.163 ; 30.563,3.33 30.563,3.33 ; 34.189,3.096 34.189,3.096
  text "50ohm impedance bottom" at 29.06,-1.778 h0.89
Top Placement:
  circle w0.1: c38.28,37.3 r2.5
  rectangle: 23,0.1 34,1.7
  lines w0.1: 28.27,0.2 28.27,28.2 ; 34.67,0.2 34.67,28.2 ; 35.38,0.2 35.38,28.2
  text "H=2.0mm" at 27.6,0 h0.89 r270
  text "H=1.1mm" at 33.75,0 h0.89 r270
  text "H=1.0mm" at 34.96,0 h0.89 r270
Via Capping Top:
  text "Capped vias top" at 29.21,-1.778 h0.89
Bottom Via Capping:
  text "Capped vias bottom" at 29.21,-1.778 h0.89

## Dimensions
0,0.1 to 0,50.5 on Dimension
0,0.1 to 50.8,0.1 on Dimension
50.8,0.1 to 50.8,38.8 on Dimension
38.8,44.3 to 0,50.5 on Dimension
44.3,44.3 to 43.18,43.18 on Dimension
38.28,37.3 to 50.8,38.8 on Dimension
38.28,37.3 to 38.8,50.5 on Dimension
0,0.1 to 1.56,9.68 on Dimension
0,0.1 to 1.56,12.28 on Dimension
